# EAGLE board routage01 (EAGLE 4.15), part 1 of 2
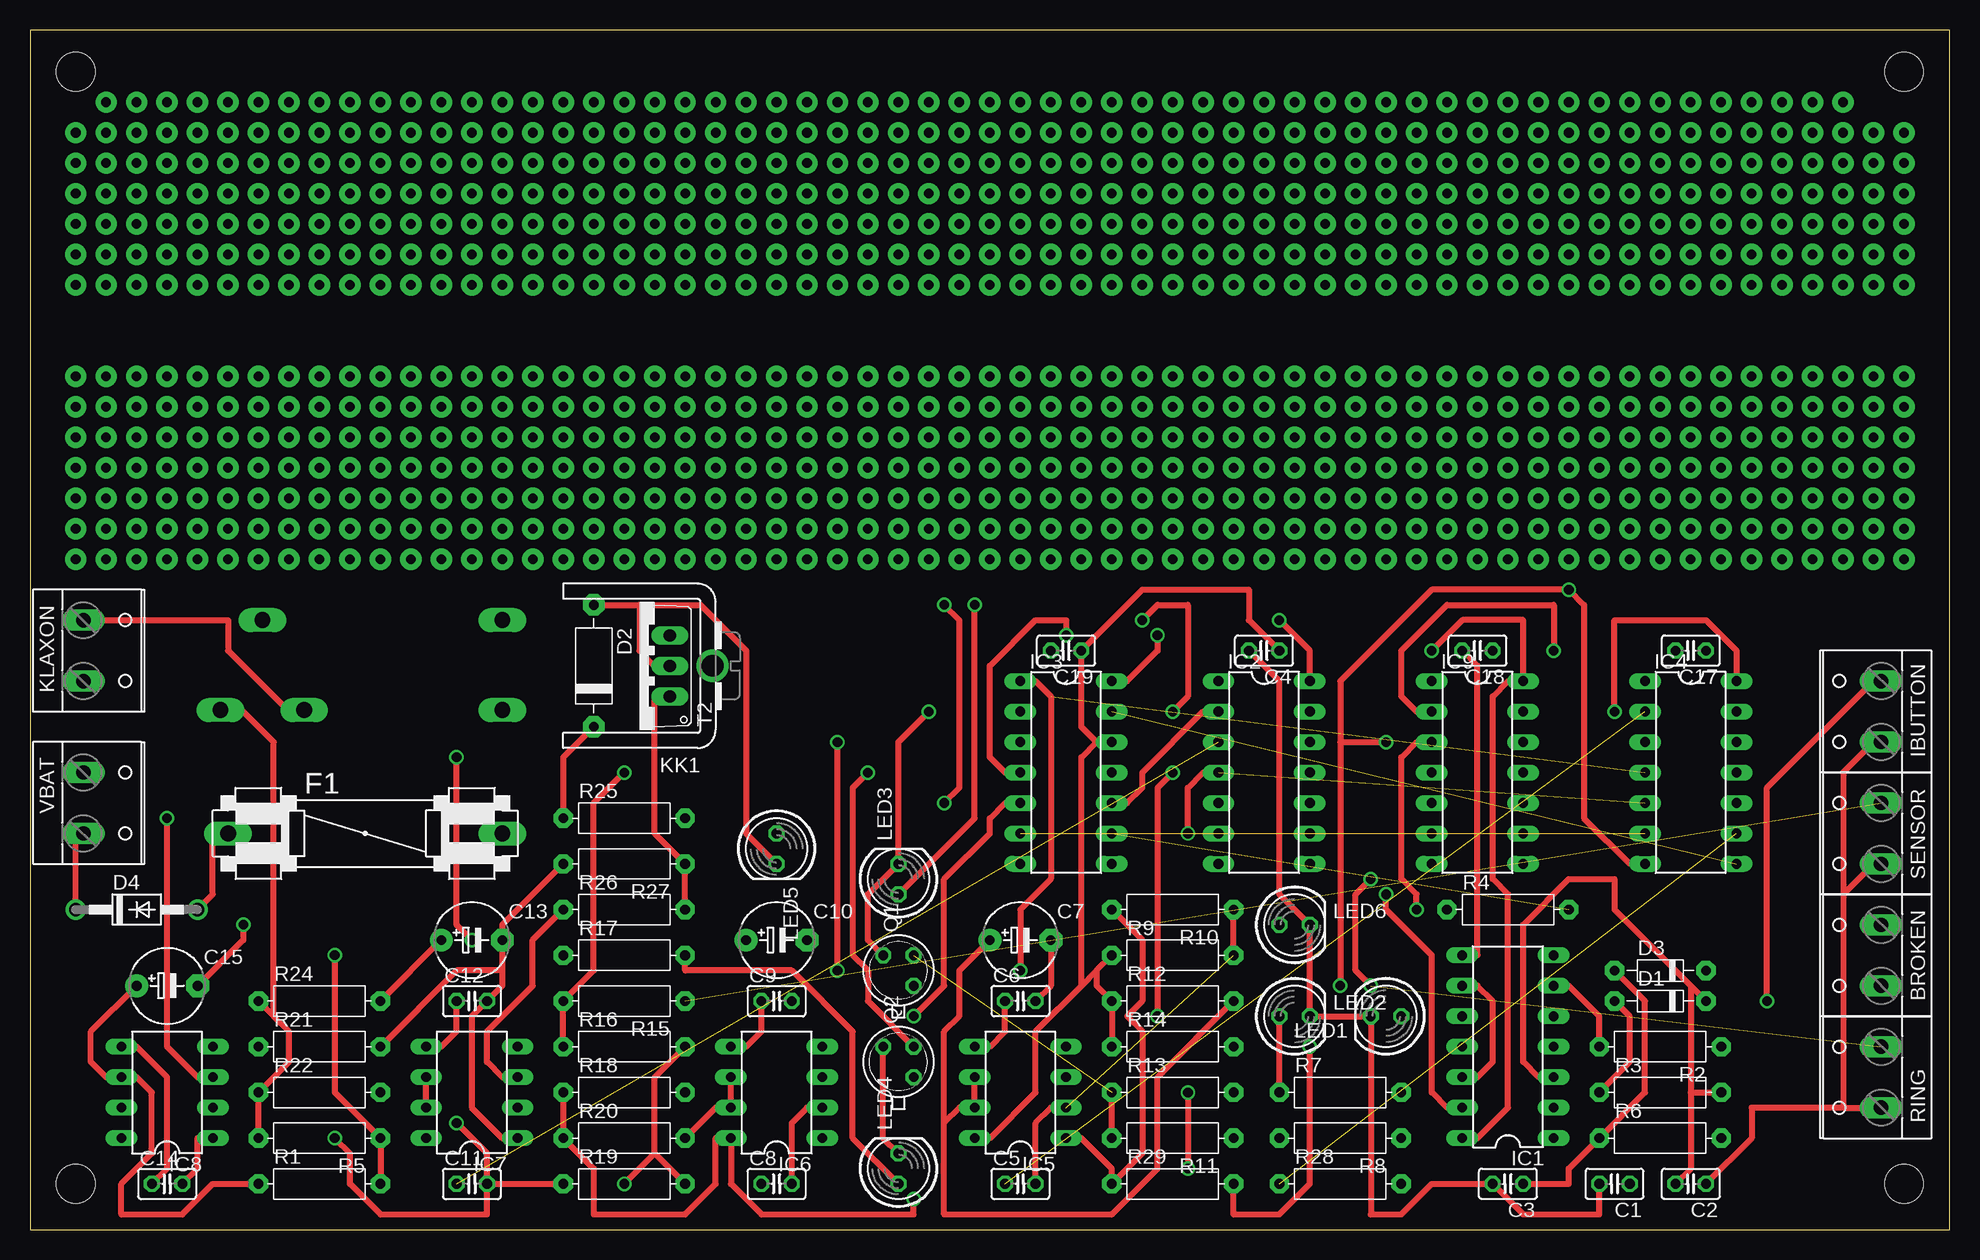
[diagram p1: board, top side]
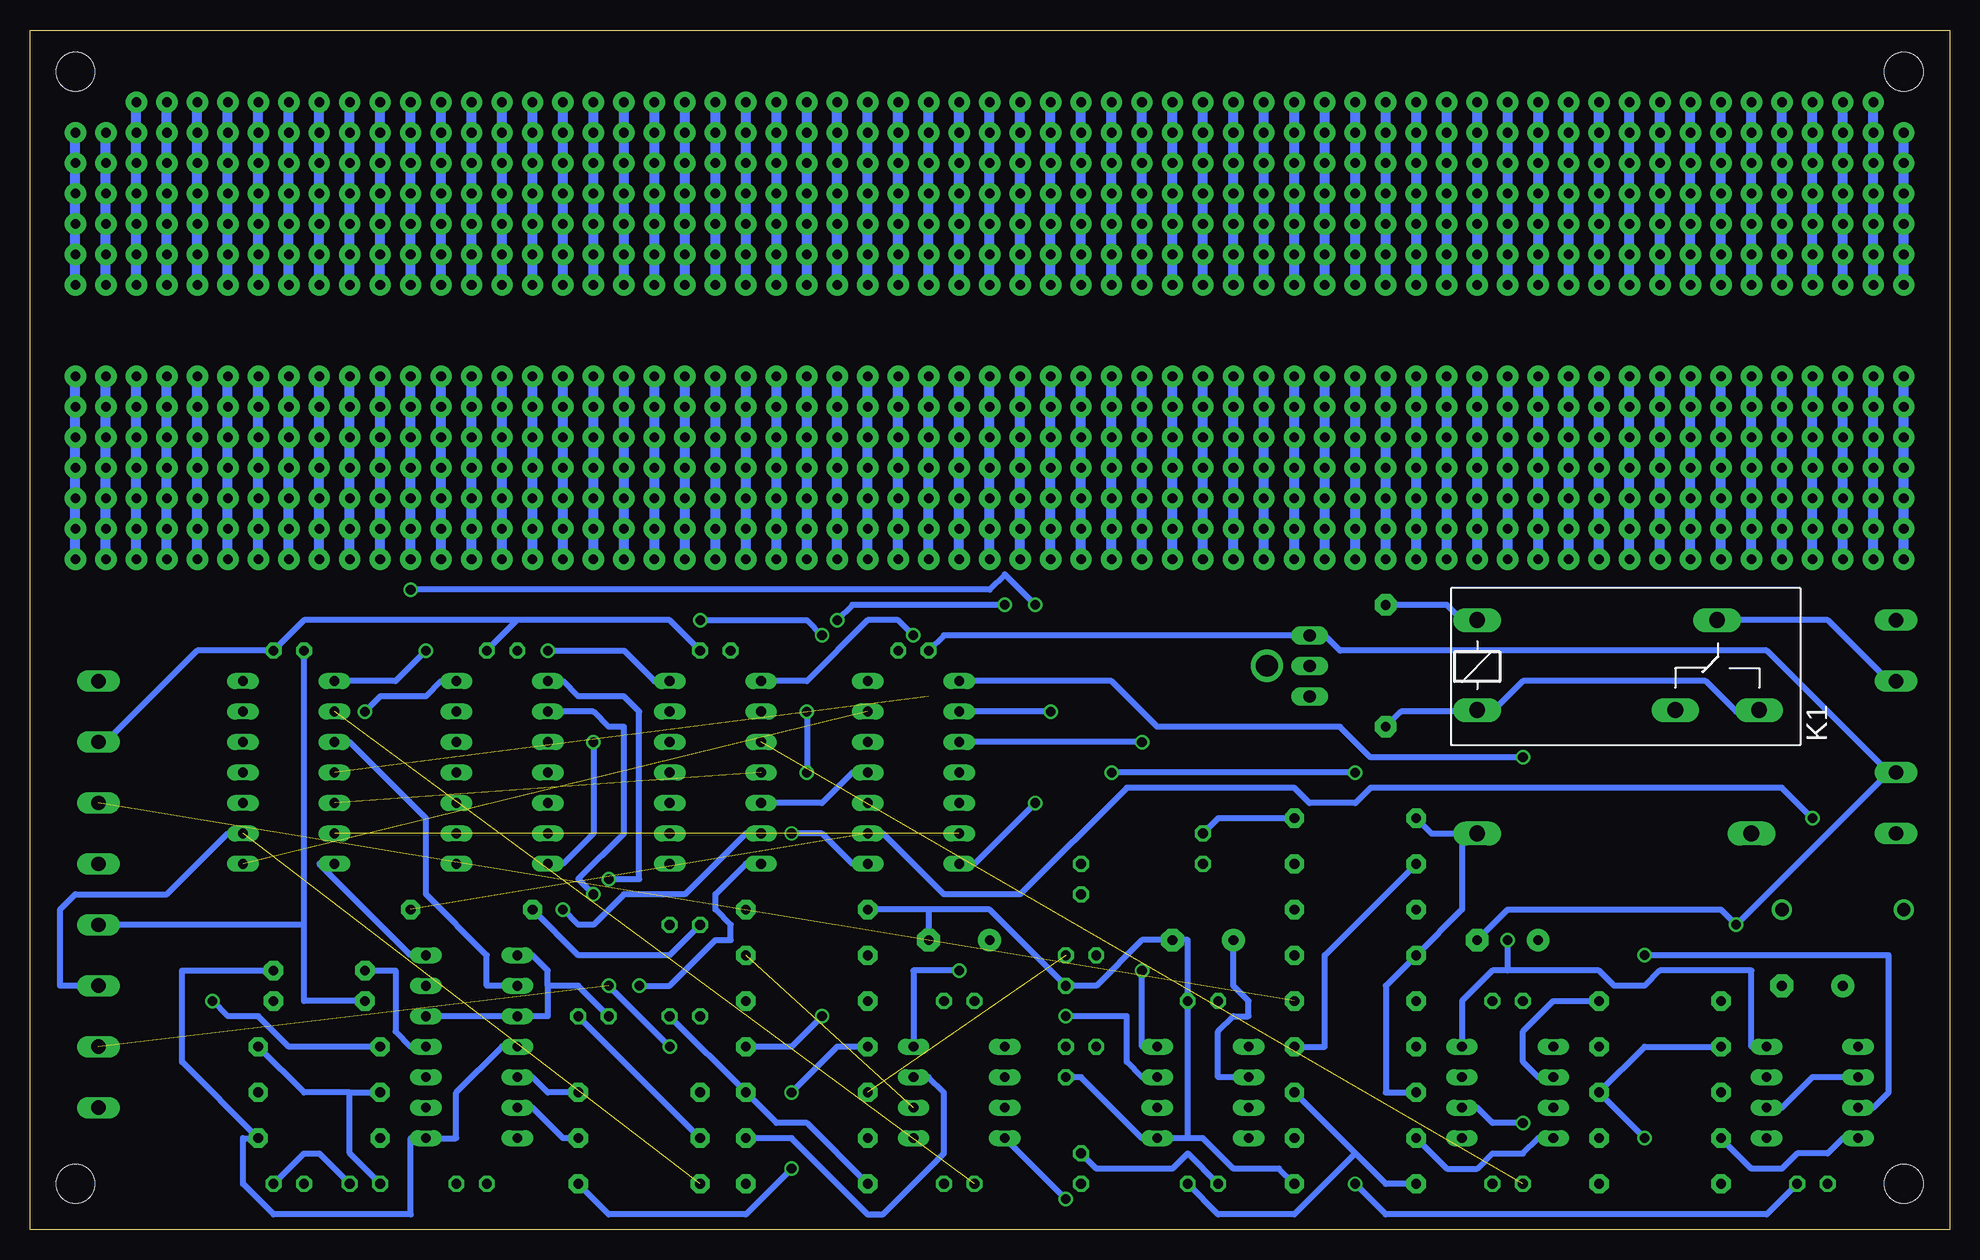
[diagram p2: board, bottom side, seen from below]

Size 160 x 100 mm. Coordinates in mm from the lower left corner, seen from the top.
Outline: 0,0 160,0 160,100 0,100 0,0
Copper layers (1*16): Top 0.035mm / dielectric 1.5mm / Bottom 0.035mm
Design rules "default": minimum track width 10mil, minimum drill 24mil, track to track 8mil, track to pad 8mil, pad to pad 8mil, via to via 8mil, smd to smd 8mil, copper to edge 40mil, drill to drill 8mil, minimum pad ring 10mil, minimum via ring 8mil, stop-mask expansion 4mil, vias tented up to drill 0mil, thermal gap 10mil
Net classes: 0 default: width 0.5 mm, drill 0.5 mm, clearance 0.8 mm
Holes 3.2 mm at 156.21,3.81 156.21,96.52 3.81,96.52 3.81,3.81

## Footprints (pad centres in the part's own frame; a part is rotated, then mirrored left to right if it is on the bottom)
W237-132 = drill 1.194 long: 1 -2.54,-0.635; 2 2.54,-0.635
C025-025X050 = drill 0.813 octagon: 1 -1.27,0; 2 1.27,0
E5-6 = drill 0.813 pad 1.905 round: + -2.54,0 | drill 0.813 pad 1.905 octagon: - 2.54,0
D-7,5 = drill 0.813 pad 1.6 octagon: 1 -3.81,0; 2 3.81,0
D-10 = drill 0.813 pad 1.778 octagon: 1 -5.08,0; 2 5.08,0
DO41-10 = drill 1.118 round: A 5.08,0; C -5.08,0
FUSE = drill 1.321 long: 1 -11.43,0; 2 11.43,0
DIL14 = drill 0.813 long: 1 -7.62,-3.81; 2 -5.08,-3.81; 3 -2.54,-3.81; 4 0,-3.81; 5 2.54,-3.81; 6 5.08,-3.81; 7 7.62,-3.81; 8 7.62,3.81; 9 5.08,3.81; 10 2.54,3.81; 11 0,3.81; 12 -2.54,3.81; 13 -5.08,3.81; 14 -7.62,3.81
DIL08 = drill 0.813 long: 1 -3.81,-3.81; 2 -1.27,-3.81; 3 1.27,-3.81; 4 3.81,-3.81; 5 3.81,3.81; 6 1.27,3.81; 7 -1.27,3.81; 8 -3.81,3.81
G2R = drill 1.321 long: 1 -2.54,-3.683; 2 -2.54,3.81; O 13.97,-3.683; P 17.45,3.81; S 20.955,-3.683
D01PA = drill 1.803 pad 2.54 round: B 0,-1.016
LED5MM = drill 0.813 octagon: A -1.27,0; K 1.27,0
TO18A = drill 0.813 octagon: B 1.27,-1.27; C 1.27,1.27; E -1.27,-1.27
R-10 = drill 0.813 pad 1.6 octagon: 1 -5.08,0; 2 5.08,0
TO220V = drill 1.016 long: 1 -2.54,-2.54; 2 0,-2.54; 3 2.54,-2.54

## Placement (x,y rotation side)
BROKEN  [W237-132]  153.67,22.86 90 top
C1  [C025-025X050]  132.08,3.81 180 top
C2  [C025-025X050]  138.43,3.81 180 top
C3  [C025-025X050]  123.19,3.81 180 top
C4  [C025-025X050]  102.87,48.26 180 top
C5  [C025-025X050]  82.55,3.81 0 top
C6  [C025-025X050]  82.55,19.05 0 top
C7  [E5-6]  82.55,24.13 0 top
C8  [C025-025X050]  62.23,3.81 0 top
C9  [C025-025X050]  62.23,19.05 0 top
C10  [E5-6]  62.23,24.13 0 top
C11  [C025-025X050]  36.83,3.81 0 top
C12  [C025-025X050]  36.83,19.05 0 top
C13  [E5-6]  36.83,24.13 0 top
C14  [C025-025X050]  11.43,3.81 0 top
C15  [E5-6]  11.43,20.32 0 top
C17  [C025-025X050]  138.43,48.26 180 top
C18  [C025-025X050]  120.65,48.26 180 top
C19  [C025-025X050]  86.36,48.26 180 top
D1  [D-7,5]  135.89,19.05 0 top
D2  [D-10]  46.99,46.99 270 top
D3  [D-7,5]  135.89,21.59 0 top
D4  1N4004  [DO41-10]  8.89,26.67 0 top
F1  [FUSE]  27.94,33.02 0 top
IBUTTON  [W237-132]  153.67,43.18 90 top
IC1  4013N  [DIL14]  123.19,15.24 90 top
IC2  4071N  [DIL14]  102.87,38.1 270 top
IC3  4081N  [DIL14]  86.36,38.1 270 top
IC4  4069N  [DIL14]  138.43,38.1 270 top
IC5  NE555N  [DIL08]  82.55,11.43 90 top
IC6  NE555N  [DIL08]  62.23,11.43 90 top
IC7  NE555N  [DIL08]  36.83,11.43 90 top
IC8  NE555N  [DIL08]  11.43,11.43 90 top
IC9  4081N  [DIL14]  120.65,38.1 270 top
K1  G2R  [G2R]  36.83,46.99 0 bottom
KK1  D01PA  [D01PA]  55.88,46.99 90 top
KLAXON  [W237-132]  5.08,48.26 270 top
LED1  [LED5MM]  113.03,17.78 180 top
LED2  [LED5MM]  105.41,17.78 0 top
LED3  [LED5MM]  72.39,29.21 90 top
LED4  [LED5MM]  72.39,5.08 90 top
LED5  [LED5MM]  62.23,31.75 270 top
LED6  [LED5MM]  105.41,25.4 0 top
Q1  2N2222  [TO18A]  72.39,21.59 90 top
Q2  2N2222  [TO18A]  72.39,13.97 90 top
R1  [R-10]  24.13,3.81 0 top
R2  [R-10]  135.89,15.24 180 top
R3  [R-10]  135.89,11.43 0 top
R4  [R-10]  123.19,26.67 0 top
R5  [R-10]  24.13,7.62 180 top
R6  [R-10]  135.89,7.62 0 top
R7  [R-10]  109.22,11.43 0 top
R8  [R-10]  109.22,7.62 180 top
R9  [R-10]  95.25,22.86 0 top
R10  [R-10]  95.25,26.67 180 top
R11  [R-10]  95.25,7.62 180 top
R12  [R-10]  95.25,19.05 0 top
R13  [R-10]  95.25,11.43 0 top
R14  [R-10]  95.25,15.24 0 top
R15  [R-10]  49.53,19.05 180 top
R16  [R-10]  49.53,15.24 0 top
R17  [R-10]  49.53,22.86 0 top
R18  [R-10]  49.53,11.43 0 top
R19  [R-10]  49.53,3.81 0 top
R20  [R-10]  49.53,7.62 0 top
R21  [R-10]  24.13,15.24 0 top
R22  [R-10]  24.13,11.43 0 top
R24  [R-10]  24.13,19.05 0 top
R25  [R-10]  49.53,34.29 0 top
R26  [R-10]  49.53,26.67 0 top
R27  [R-10]  49.53,30.48 180 top
R28  [R-10]  109.22,3.81 0 top
R29  [R-10]  95.25,3.81 0 top
RING  [W237-132]  153.67,12.7 90 top
SENSOR  [W237-132]  153.67,33.02 90 top
T2  [TO220V]  50.8,46.99 90 top
VBAT  [W237-132]  5.08,35.56 270 top

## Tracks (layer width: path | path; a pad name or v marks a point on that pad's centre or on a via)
ACTION  (via drill 0.8)
  Top 0.5: v73.66,17.78 76.2,20.32 76.2,29.21 80.01,33.02 80.01,34.29 81.28,35.56 IC3.5
  Bottom 0.5: v73.66,17.78 68.58,17.78 68.58,13.97 67.31,12.7 IC6.3
ALERTE  (via drill 0.8)  (1 unrouted)
  Top 0.5: v96.52,33.02 96.52,36.83 97.79,38.1 IC2.4
  Bottom 0.5: v96.52,33.02 93.98,33.02 91.44,30.48 IC3.8
ARRACHEMENT  (1 unrouted)
  Bottom 0.5: IC4.9 143.51,33.02 148.59,27.94 156.21,27.94 157.48,26.67 157.48,20.32 BROKEN.1
BP_URGENCE  (via drill 0.8)  (1 unrouted)
  Top 0.5: v111.76,29.21 110.49,27.94 110.49,21.59 v111.76,20.32 | v106.68,15.24 106.68,3.81 104.14,1.27 100.33,1.27 R29.2
  Bottom 0.5: v111.76,29.21 109.22,29.21 109.22,43.18 110.49,44.45 114.3,44.45 115.57,45.72 IC9.1 | v106.68,15.24 v111.76,20.32
CDE
  Top 0.5: R26.1 41.91,24.13 41.91,20.32 38.1,16.51 38.1,13.97 39.37,12.7 IC7.3
CLEAR  (via drill 0.8)
  Top 0.5: v67.31,21.59 v67.31,40.64
  Bottom 0.5: v67.31,21.59 67.31,15.24 IC6.4 | v67.31,40.64 IC3.3
GND  (via drill 0.8)
  Top 0.5: C1.2 130.81,1.27 124.46,1.27 C3.2 116.84,3.81 114.3,1.27 111.76,1.27 LED1.K LED2.K LED6.K 104.14,27.94 104.14,45.72 C4.2 | R3.1 133.35,13.97 133.35,17.78 D1.1 | C18.2 120.65,46.99 120.65,22.86 IC1.8 | IC5.1 87.63,7.62 90.17,5.08 R29.1 92.71,6.35 92.71,16.51 91.44,17.78 92.71,19.05 92.71,24.13 R10.2 | 39.37,21.59 C13.- 39.37,25.4 R27.2 | 39.37,21.59 39.37,20.32 C12.2 36.83,17.78 36.83,10.16 39.37,7.62 IC7.1 | R21.2 35.56,21.59 39.37,21.59 | C6.2 85.09,20.32 C7.- | C14.2 13.97,5.08 13.97,7.62 IC8.1 | R16.2 52.07,12.7 52.07,6.35 | 52.07,6.35 R19.2 | v49.53,3.81 52.07,6.35 | C15.- 17.78,24.13 v17.78,25.4
  Bottom 0.5: 137.16,25.4 137.16,19.05 D1.1 | 137.16,25.4 C17.2 | R2.1 137.16,11.43 133.35,11.43 | 133.35,11.43 R3.1 | 137.16,25.4 BROKEN.2 | C1.2 133.35,6.35 133.35,11.43 | IC1.5 IC1.10 116.84,17.78 116.84,20.32 | 116.84,20.32 116.84,21.59 118.11,22.86 IC1.8 | LED2.K R13.2 97.79,8.89 95.25,8.89 R29.1 | 116.84,20.32 114.3,20.32 LED1.K | 85.09,26.67 R10.2 | 85.09,26.67 80.01,26.67 Q1.E 71.12,20.32 67.31,24.13 C10.- 63.5,24.13 C9.2 63.5,7.62 | 85.09,26.67 C7.- | Q2.E 72.39,12.7 67.31,7.62 IC6.1 63.5,7.62 | R19.2 55.88,5.08 59.69,5.08 62.23,7.62 63.5,7.62 | C14.2 15.24,1.27 46.99,1.27 v49.53,3.81 | R27.2 52.07,22.86 52.07,15.24 R16.2 | C19.2 83.82,49.53 T2.3 52.07,49.53 50.8,48.26 15.24,48.26 5.08,38.1 | 5.08,38.1 v17.78,25.4 19.05,26.67 36.83,26.67 C13.- | 5.08,38.1 VBAT.1
INHIBE  (via drill 0.8)
  Top 0.5: Q1.C 69.85,24.13 69.85,27.94 LED3.K 72.39,40.64 v74.93,43.18
  Bottom 0.5: v74.93,43.18 IC3.2
N$1
  Top 0.5: C3.1 128.27,3.81 128.27,5.08 R6.1 134.62,11.43 134.62,19.05 D3.1
  Bottom 0.5: D3.1 129.54,21.59 129.54,16.51 128.27,15.24 IC1.4
N$2
  Top 0.5: 138.43,20.32 D1.2 | 138.43,20.32 132.08,26.67 132.08,29.21 128.27,29.21 124.46,25.4 124.46,13.97 125.73,12.7 IC1.3 | C2.2 138.43,5.08 138.43,11.43 | 138.43,20.32 138.43,11.43 | 138.43,11.43 R3.2
N$3
  Top 0.5: LED4.A 68.58,7.62 68.58,16.51 63.5,21.59 54.61,21.59 R17.2
N$4
  Top 0.5: R7.1 LED2.A
N$5
  Bottom 0.5: R8.2 LED1.A
N$6  (via drill 0.8)
  Top 0.5: R2.2 130.81,17.78 128.27,20.32 IC1.6 | v144.78,19.05 144.78,36.83 153.67,45.72 IBUTTON.2
  Bottom 0.5: v144.78,19.05 143.51,17.78 140.97,17.78 138.43,15.24 R2.2
N$7
  Bottom 0.5: IC1.11 120.65,15.24 124.46,11.43 124.46,7.62 IC1.1 128.27,7.62 128.27,1.27 139.7,1.27 142.24,3.81 142.24,7.62 R6.2 147.32,13.97 147.32,21.59 D3.2
N$8
  Top 0.5: C6.1 81.28,16.51 80.01,15.24 IC5.5
N$9
  Top 0.5: IC5.6 IC5.7 77.47,10.16 76.2,8.89 | R12.2 93.98,12.7 93.98,5.08 90.17,1.27 76.2,1.27 76.2,8.89 | C7.+ 77.47,21.59 77.47,17.78 76.2,16.51 76.2,8.89
N$10
  Top 0.5: Q2.C 71.12,7.62 LED4.K
  Bottom 0.5: C8.1 63.5,6.35 64.77,5.08 71.12,5.08 LED4.K
N$11
  Bottom 0.5: R11.1 96.52,7.62 90.17,1.27 88.9,1.27 83.82,6.35 83.82,11.43 85.09,12.7 IC5.3
N$12  (1 unrouted)
  Top 0.5: R11.2 R13.1
N$13  (via drill 0.8)
  Top 0.5: Q2.B 69.85,19.05 69.85,21.59 68.58,22.86 68.58,36.83 v69.85,38.1 | v49.53,38.1 46.99,35.56 46.99,21.59 R15.2 R16.1
  Bottom 0.5: v49.53,38.1 v69.85,38.1
N$14  (1 unrouted)
  Top 0.5: R9.2 R10.1 | C5.2 83.82,8.89 85.09,10.16 IC5.2
N$15  (1 unrouted)
N$16
  Top 0.5: C12.1 35.56,16.51 34.29,15.24 IC7.5
N$17
  Top 0.5: C9.1 60.96,16.51 59.69,15.24 IC6.5
N$18  (via drill 0.8)
  Top 0.5: C8.2 63.5,8.89 64.77,10.16 IC6.2 | C11.2 R19.1 | v35.56,8.89 38.1,6.35 C11.2 | v25.4,7.62 26.67,6.35 26.67,3.81 29.21,1.27 38.1,1.27 C11.2
  Bottom 0.5: R21.1 25.4,15.24 R22.2 v25.4,7.62 | v35.56,8.89 38.1,8.89 39.37,10.16 IC7.2 | 49.53,6.35 46.99,3.81 R19.1 | 49.53,6.35 R18.2 | C8.2 60.96,1.27 54.61,1.27 49.53,6.35
N$19  (via drill 0.8)
  Top 0.5: LED3.A 78.74,34.29 v78.74,52.07 | v92.71,50.8 93.98,52.07 96.52,52.07 96.52,44.45 v95.25,43.18 | v95.25,38.1 93.98,36.83 v93.98,17.78
  Bottom 0.5: v78.74,52.07 91.44,52.07 v92.71,50.8 | v95.25,43.18 v95.25,38.1 | v93.98,17.78 96.52,15.24 R14.2
N$20
  Bottom 0.5: LED6.A 106.68,22.86 114.3,22.86 R4.1
N$21
  Top 0.5: T2.1 52.07,44.45 52.07,33.02 R27.1 R26.2
N$22  (1 unrouted)
N$23
  Top 0.5: IC7.7 IC7.6 | R24.2 C13.+
  Bottom 0.5: R24.2 33.02,19.05 35.56,16.51 35.56,13.97 34.29,12.7 IC7.6
N$24
  Top 0.5: LED5.K 59.69,33.02 59.69,48.26 55.88,52.07 50.8,52.07 | D2.1 50.8,52.07 | 50.8,52.07 50.8,48.26 52.07,46.99 T2.2
  Bottom 0.5: D2.1 41.91,52.07 40.64,50.8 K1.2
N$25
  Bottom 0.5: LED5.A 60.96,34.29 R25.2
N$26
  Top 0.5: IC3.10 91.44,35.56 92.71,36.83 92.71,38.1 97.79,43.18 IC2.2
N$27  (via drill 0.8)
  Top 0.5: v86.36,49.53 86.36,50.8 83.82,50.8 80.01,46.99 80.01,39.37 81.28,38.1 IC3.4
  Bottom 0.5: v86.36,49.53 87.63,50.8 90.17,50.8 95.25,45.72 IC2.1
N$28
  Top 0.5: IC6.6 IC6.7 57.15,10.16 R20.2
  Bottom 0.5: C10.+ 59.69,20.32 58.42,19.05 58.42,17.78 59.69,17.78 60.96,16.51 60.96,12.7 IC6.6
N$29  (1 unrouted)
N$30
  Top 0.5: C14.1 11.43,5.08 11.43,12.7 8.89,15.24 IC8.5
N$31  (via drill 0.8)
  Top 0.5: v25.4,22.86 25.4,11.43 R5.1 R1.2
  Bottom 0.5: v25.4,22.86 5.08,22.86 5.08,11.43 6.35,10.16 IC8.7
N$32
  Bottom 0.5: IC3.11 91.44,38.1 93.98,35.56 IC2.5
N$33  (via drill 0.8)
  Top 0.5: v115.57,26.67 115.57,27.94 114.3,29.21 114.3,39.37 115.57,40.64 IC9.3
  Bottom 0.5: v115.57,26.67 114.3,25.4 113.03,25.4 110.49,27.94 105.41,27.94 100.33,33.02 IC2.6
N$34
  Top 0.5: R1.1 15.24,3.81 12.7,1.27 7.62,1.27 7.62,3.81 10.16,6.35 10.16,11.43 8.89,12.7 IC8.6 6.35,12.7 5.08,13.97 5.08,16.51 C15.+
  Bottom 0.5: IC8.2 13.97,10.16 11.43,12.7 IC8.6
N$35
  Top 0.5: D4.A 15.24,27.94 15.24,33.02 F1.1
N$36
  Top 0.5: KLAXON.1 16.51,50.8 16.51,48.26 21.59,43.18 K1.O
N$37
  Top 0.5: D4.C 3.81,33.02 VBAT.2
N$38
  Bottom 0.5: KLAXON.2 5.08,45.72 10.16,50.8 K1.P
N$44  (via drill 0.8 pad 1.78)
  other vias: 92.71,81.28
N$45  (via drill 0.8 pad 1.78)
  other vias: 90.17,83.82
N$46  (via drill 0.8 pad 1.78)
  other vias: 92.71,78.74
N$47  (via drill 0.8 pad 1.78)
  other vias: 113.03,71.12
N$48  (via drill 0.8 pad 1.78)
  other vias: 113.03,68.58
N$49  (via drill 0.8 pad 1.78)
  other vias: 92.71,71.12
N$50  (via drill 0.8 pad 1.78)
  other vias: 92.71,68.58
N$51  (via drill 0.8 pad 1.78)
  other vias: 92.71,66.04
N$52  (via drill 0.8 pad 1.78)
  other vias: 92.71,63.5
N$53  (via drill 0.8 pad 1.78)
  other vias: 92.71,60.96
N$54  (via drill 0.8 pad 1.78)
  other vias: 92.71,58.42
N$55  (via drill 0.8 pad 1.78)
  other vias: 92.71,55.88
N$56  (via drill 0.8 pad 1.78)
  other vias: 92.71,83.82
N$57  (via drill 0.8 pad 1.78)
  other vias: 95.25,83.82
N$58  (via drill 0.8 pad 1.78)
  other vias: 95.25,81.28
N$59  (via drill 0.8 pad 1.78)
  other vias: 95.25,78.74
N$60  (via drill 0.8 pad 1.78)
  other vias: 97.79,83.82
N$61  (via drill 0.8 pad 1.78)
  other vias: 100.33,83.82
N$62  (via drill 0.8 pad 1.78)
  other vias: 100.33,81.28
N$63  (via drill 0.8 pad 1.78)
  other vias: 100.33,78.74
N$64  (via drill 0.8 pad 1.78)
  other vias: 113.03,66.04
N$65  (via drill 0.8 pad 1.78)
  other vias: 113.03,63.5
N$66  (via drill 0.8 pad 1.78)
  other vias: 100.33,71.12
N$67  (via drill 0.8 pad 1.78)
  other vias: 100.33,68.58
N$68  (via drill 0.8 pad 1.78)
  other vias: 97.79,81.28
N$69  (via drill 0.8 pad 1.78)
  other vias: 97.79,78.74
N$70  (via drill 0.8 pad 1.78)
  other vias: 115.57,63.5
N$71  (via drill 0.8 pad 1.78)
  other vias: 102.87,83.82
N$72  (via drill 0.8 pad 1.78)
  other vias: 105.41,83.82
N$73  (via drill 0.8 pad 1.78)
  other vias: 107.95,83.82
N$74  (via drill 0.8 pad 1.78)
  other vias: 110.49,83.82
N$75  (via drill 0.8 pad 1.78)
  other vias: 113.03,83.82
N$76  (via drill 0.8 pad 1.78)
  other vias: 115.57,83.82
N$77  (via drill 0.8 pad 1.78)
  other vias: 118.11,83.82
N$78  (via drill 0.8 pad 1.78)
  other vias: 120.65,83.82
N$79  (via drill 0.8 pad 1.78)
  other vias: 123.19,83.82
N$80  (via drill 0.8 pad 1.78)
  other vias: 125.73,83.82
N$81  (via drill 0.8 pad 1.78)
  other vias: 102.87,81.28
N$82  (via drill 0.8 pad 1.78)
  other vias: 105.41,81.28
N$83  (via drill 0.8 pad 1.78)
  other vias: 105.41,78.74
N$84  (via drill 0.8 pad 1.78)
  other vias: 115.57,71.12
N$85  (via drill 0.8 pad 1.78)
  other vias: 102.87,78.74
N$86  (via drill 0.8 pad 1.78)
  other vias: 118.11,71.12
N$87  (via drill 0.8 pad 1.78)
  other vias: 120.65,71.12
N$88  (via drill 0.8 pad 1.78)
  other vias: 120.65,68.58
N$89  (via drill 0.8 pad 1.78)
  other vias: 105.41,71.12
N$90  (via drill 0.8 pad 1.78)
  other vias: 102.87,71.12
N$91  (via drill 0.8 pad 1.78)
  other vias: 102.87,68.58
N$92  (via drill 0.8 pad 1.78)
  other vias: 105.41,68.58
N$93  (via drill 0.8 pad 1.78)
  other vias: 105.41,66.04
N$94  (via drill 0.8 pad 1.78)
  other vias: 102.87,66.04
N$95  (via drill 0.8 pad 1.78)
  other vias: 100.33,66.04
N$96  (via drill 0.8 pad 1.78)
  other vias: 100.33,63.5
N$97  (via drill 0.8 pad 1.78)
  other vias: 100.33,60.96
N$98  (via drill 0.8 pad 1.78)
  other vias: 100.33,58.42
N$99  (via drill 0.8 pad 1.78)
  other vias: 95.25,55.88
N$100  (via drill 0.8 pad 1.78)
  other vias: 95.25,58.42
N$101  (via drill 0.8 pad 1.78)
  other vias: 95.25,60.96
N$102  (via drill 0.8 pad 1.78)
  other vias: 95.25,63.5
N$103  (via drill 0.8 pad 1.78)
  other vias: 95.25,66.04
N$104  (via drill 0.8 pad 1.78)
  other vias: 95.25,68.58
N$105  (via drill 0.8 pad 1.78)
  other vias: 95.25,71.12
N$106  (via drill 0.8 pad 1.78)
  other vias: 120.65,66.04
N$107  (via drill 0.8 pad 1.78)
  other vias: 118.11,68.58
N$108  (via drill 0.8 pad 1.78)
  other vias: 115.57,68.58
N$109  (via drill 0.8 pad 1.78)
  other vias: 97.79,71.12
N$110  (via drill 0.8 pad 1.78)
  other vias: 97.79,68.58
N$111  (via drill 0.8 pad 1.78)
  other vias: 97.79,66.04
N$112  (via drill 0.8 pad 1.78)
  other vias: 97.79,63.5
N$113  (via drill 0.8 pad 1.78)
  other vias: 97.79,60.96
N$114  (via drill 0.8 pad 1.78)
  other vias: 97.79,58.42
N$115  (via drill 0.8 pad 1.78)
  other vias: 97.79,55.88
N$116  (via drill 0.8 pad 1.78)
  other vias: 107.95,81.28
N$117  (via drill 0.8 pad 1.78)
  other vias: 107.95,78.74
N$118  (via drill 0.8 pad 1.78)
  other vias: 125.73,71.12
N$119  (via drill 0.8 pad 1.78)
  other vias: 125.73,68.58
N$120  (via drill 0.8 pad 1.78)
  other vias: 107.95,71.12
N$121  (via drill 0.8 pad 1.78)
  other vias: 107.95,68.58
N$122  (via drill 0.8 pad 1.78)
  other vias: 107.95,66.04
N$123  (via drill 0.8 pad 1.78)
  other vias: 107.95,63.5
N$124  (via drill 0.8 pad 1.78)
  other vias: 107.95,60.96
N$125  (via drill 0.8 pad 1.78)
  other vias: 107.95,58.42
N$126  (via drill 0.8 pad 1.78)
  other vias: 107.95,55.88
N$127  (via drill 0.8 pad 1.78)
  other vias: 105.41,55.88
N$128  (via drill 0.8 pad 1.78)
  other vias: 102.87,55.88
N$129  (via drill 0.8 pad 1.78)
  other vias: 105.41,58.42
N$130  (via drill 0.8 pad 1.78)
  other vias: 105.41,60.96
N$131  (via drill 0.8 pad 1.78)
  other vias: 105.41,63.5
N$132  (via drill 0.8 pad 1.78)
  other vias: 102.87,63.5
N$133  (via drill 0.8 pad 1.78)
  other vias: 102.87,60.96
N$134  (via drill 0.8 pad 1.78)
  other vias: 102.87,58.42
N$135  (via drill 0.8 pad 1.78)
  other vias: 110.49,55.88
N$136  (via drill 0.8 pad 1.78)
  other vias: 113.03,55.88
N$137  (via drill 0.8 pad 1.78)
  other vias: 115.57,55.88
N$138  (via drill 0.8 pad 1.78)
  other vias: 118.11,55.88
N$139  (via drill 0.8 pad 1.78)
  other vias: 120.65,55.88
N$140  (via drill 0.8 pad 1.78)
  other vias: 123.19,55.88
N$141  (via drill 0.8 pad 1.78)
  other vias: 125.73,55.88
N$142  (via drill 0.8 pad 1.78)
  other vias: 128.27,55.88
N$143  (via drill 0.8 pad 1.78)
  other vias: 130.81,55.88
N$144  (via drill 0.8 pad 1.78)
  other vias: 133.35,55.88
N$145  (via drill 0.8 pad 1.78)
  other vias: 135.89,55.88
N$146  (via drill 0.8 pad 1.78)
  other vias: 138.43,55.88
N$147  (via drill 0.8 pad 1.78)
  other vias: 140.97,55.88
N$148  (via drill 0.8 pad 1.78)
  other vias: 143.51,55.88
N$149  (via drill 0.8 pad 1.78)
  other vias: 146.05,55.88
N$150  (via drill 0.8 pad 1.78)
  other vias: 148.59,55.88
N$151  (via drill 0.8 pad 1.78)
  other vias: 151.13,55.88
N$152  (via drill 0.8 pad 1.78)
  other vias: 153.67,55.88
N$153  (via drill 0.8 pad 1.78)
  other vias: 156.21,55.88
N$154  (via drill 0.8 pad 1.78)
  other vias: 156.21,58.42
N$155  (via drill 0.8 pad 1.78)
  other vias: 153.67,58.42
N$156  (via drill 0.8 pad 1.78)
  other vias: 110.49,81.28
N$157  (via drill 0.8 pad 1.78)
  other vias: 110.49,58.42
N$158  (via drill 0.8 pad 1.78)
  other vias: 110.49,60.96
N$159  (via drill 0.8 pad 1.78)
  other vias: 110.49,63.5
N$160  (via drill 0.8 pad 1.78)
  other vias: 110.49,66.04
N$161  (via drill 0.8 pad 1.78)
  other vias: 110.49,68.58
N$162  (via drill 0.8 pad 1.78)
  other vias: 110.49,71.12
N$163  (via drill 0.8 pad 1.78)
  other vias: 125.73,66.04
N$164  (via drill 0.8 pad 1.78)
  other vias: 125.73,63.5
N$165  (via drill 0.8 pad 1.78)
  other vias: 110.49,78.74
N$166  (via drill 0.8 pad 1.78)
  other vias: 125.73,78.74
N$167  (via drill 0.8 pad 1.78)
  other vias: 64.77,55.88
N$168  (via drill 0.8 pad 1.78)
  other vias: 62.23,55.88
N$169  (via drill 0.8 pad 1.78)
  other vias: 123.19,71.12
N$170  (via drill 0.8 pad 1.78)
  other vias: 123.19,68.58
N$171  (via drill 0.8 pad 1.78)
  other vias: 123.19,66.04
N$172  (via drill 0.8 pad 1.78)
  other vias: 123.19,63.5
N$173  (via drill 0.8 pad 1.78)
  other vias: 123.19,58.42
N$174  (via drill 0.8 pad 1.78)
  other vias: 120.65,58.42
N$175  (via drill 0.8 pad 1.78)
  other vias: 128.27,58.42
N$176  (via drill 0.8 pad 1.78)
  other vias: 128.27,60.96
N$177  (via drill 0.8 pad 1.78)
  other vias: 125.73,58.42
N$178  (via drill 0.8 pad 1.78)
  other vias: 125.73,60.96
N$179  (via drill 0.8 pad 1.78)
  other vias: 123.19,60.96
N$180  (via drill 0.8 pad 1.78)
  other vias: 113.03,60.96
N$181  (via drill 0.8 pad 1.78)
  other vias: 115.57,60.96
N$182  (via drill 0.8 pad 1.78)
  other vias: 118.11,60.96
N$183  (via drill 0.8 pad 1.78)
  other vias: 120.65,60.96
N$184  (via drill 0.8 pad 1.78)
  other vias: 120.65,63.5
N$185  (via drill 0.8 pad 1.78)
  other vias: 118.11,63.5
N$186  (via drill 0.8 pad 1.78)
  other vias: 133.35,60.96
N$187  (via drill 0.8 pad 1.78)
  other vias: 118.11,66.04
N$188  (via drill 0.8 pad 1.78)
  other vias: 115.57,66.04
N$189  (via drill 0.8 pad 1.78)
  other vias: 135.89,60.96
N$190  (via drill 0.8 pad 1.78)
  other vias: 135.89,63.5
N$191  (via drill 0.8 pad 1.78)
  other vias: 133.35,63.5
N$192  (via drill 0.8 pad 1.78)
  other vias: 130.81,63.5
N$193  (via drill 0.8 pad 1.78)
  other vias: 128.27,63.5
N$194  (via drill 0.8 pad 1.78)
  other vias: 115.57,81.28
N$195  (via drill 0.8 pad 1.78)
  other vias: 100.33,55.88
N$196  (via drill 0.8 pad 1.78)
  other vias: 113.03,58.42
N$197  (via drill 0.8 pad 1.78)
  other vias: 118.11,58.42
N$198  (via drill 0.8 pad 1.78)
  other vias: 115.57,58.42
N$199  (via drill 0.8 pad 1.78)
  other vias: 135.89,58.42
N$200  (via drill 0.8 pad 1.78)
  other vias: 133.35,58.42
N$201  (via drill 0.8 pad 1.78)
  other vias: 130.81,58.42
N$202  (via drill 0.8 pad 1.78)
  other vias: 130.81,60.96
N$203  (via drill 0.8 pad 1.78)
  other vias: 128.27,66.04
N$204  (via drill 0.8 pad 1.78)
  other vias: 128.27,68.58
N$205  (via drill 0.8 pad 1.78)
  other vias: 128.27,71.12
N$206  (via drill 0.8 pad 1.78)
  other vias: 130.81,71.12
N$207  (via drill 0.8 pad 1.78)
  other vias: 130.81,68.58
N$208  (via drill 0.8 pad 1.78)
  other vias: 130.81,66.04
N$209  (via drill 0.8 pad 1.78)
  other vias: 133.35,66.04
N$210  (via drill 0.8 pad 1.78)
  other vias: 135.89,66.04
N$211  (via drill 0.8 pad 1.78)
  other vias: 135.89,68.58
N$212  (via drill 0.8 pad 1.78)
  other vias: 133.35,68.58
N$213  (via drill 0.8 pad 1.78)
  other vias: 133.35,71.12
N$214  (via drill 0.8 pad 1.78)
  other vias: 135.89,71.12
N$215  (via drill 0.8 pad 1.78)
  other vias: 146.05,58.42
N$216  (via drill 0.8 pad 1.78)
  other vias: 143.51,58.42
N$217  (via drill 0.8 pad 1.78)
  other vias: 140.97,58.42
N$218  (via drill 0.8 pad 1.78)
  other vias: 138.43,58.42
N$219  (via drill 0.8 pad 1.78)
  other vias: 138.43,60.96
N$220  (via drill 0.8 pad 1.78)
  other vias: 138.43,63.5
N$221  (via drill 0.8 pad 1.78)
  other vias: 138.43,66.04
N$222  (via drill 0.8 pad 1.78)
  other vias: 138.43,68.58
N$223  (via drill 0.8 pad 1.78)
  other vias: 138.43,71.12
N$224  (via drill 0.8 pad 1.78)
  other vias: 146.05,60.96
N$225  (via drill 0.8 pad 1.78)
  other vias: 146.05,63.5
N$226  (via drill 0.8 pad 1.78)
  other vias: 146.05,66.04
N$227  (via drill 0.8 pad 1.78)
  other vias: 146.05,68.58
N$228  (via drill 0.8 pad 1.78)
  other vias: 146.05,71.12
N$229  (via drill 0.8 pad 1.78)
  other vias: 143.51,71.12
N$230  (via drill 0.8 pad 1.78)
  other vias: 140.97,71.12
N$231  (via drill 0.8 pad 1.78)
  other vias: 140.97,68.58
N$232  (via drill 0.8 pad 1.78)
  other vias: 143.51,68.58
N$233  (via drill 0.8 pad 1.78)
  other vias: 143.51,66.04
N$234  (via drill 0.8 pad 1.78)
  other vias: 143.51,63.5
N$235  (via drill 0.8 pad 1.78)
  other vias: 143.51,60.96
N$236  (via drill 0.8 pad 1.78)
  other vias: 140.97,60.96
N$237  (via drill 0.8 pad 1.78)
  other vias: 140.97,63.5
N$238  (via drill 0.8 pad 1.78)
  other vias: 140.97,66.04
N$239  (via drill 0.8 pad 1.78)
  other vias: 148.59,58.42
N$240  (via drill 0.8 pad 1.78)
  other vias: 148.59,60.96
N$241  (via drill 0.8 pad 1.78)
  other vias: 151.13,58.42
N$242  (via drill 0.8 pad 1.78)
  other vias: 148.59,63.5
N$243  (via drill 0.8 pad 1.78)
  other vias: 148.59,66.04
N$244  (via drill 0.8 pad 1.78)
  other vias: 148.59,68.58
N$245  (via drill 0.8 pad 1.78)
  other vias: 148.59,71.12
N$246  (via drill 0.8 pad 1.78)
  other vias: 151.13,71.12
N$247  (via drill 0.8 pad 1.78)
  other vias: 151.13,68.58
N$248  (via drill 0.8 pad 1.78)
  other vias: 151.13,66.04
N$249  (via drill 0.8 pad 1.78)
  other vias: 151.13,63.5
N$250  (via drill 0.8 pad 1.78)
  other vias: 151.13,60.96
N$251  (via drill 0.8 pad 1.78)
  other vias: 153.67,60.96
N$252  (via drill 0.8 pad 1.78)
  other vias: 156.21,60.96
N$253  (via drill 0.8 pad 1.78)
  other vias: 156.21,63.5
N$254  (via drill 0.8 pad 1.78)
  other vias: 153.67,63.5
N$255  (via drill 0.8 pad 1.78)
  other vias: 156.21,66.04
N$256  (via drill 0.8 pad 1.78)
  other vias: 153.67,66.04
N$257  (via drill 0.8 pad 1.78)
  other vias: 153.67,68.58
N$258  (via drill 0.8 pad 1.78)
  other vias: 156.21,68.58
N$259  (via drill 0.8 pad 1.78)
  other vias: 156.21,71.12
N$260  (via drill 0.8 pad 1.78)
  other vias: 153.67,71.12
N$261  (via drill 0.8 pad 1.78)
  other vias: 90.17,55.88
N$262  (via drill 0.8 pad 1.78)
  other vias: 87.63,55.88
N$263  (via drill 0.8 pad 1.78)
  other vias: 85.09,55.88
N$264  (via drill 0.8 pad 1.78)
  other vias: 82.55,55.88
N$265  (via drill 0.8 pad 1.78)
  other vias: 80.01,55.88
N$266  (via drill 0.8 pad 1.78)
  other vias: 77.47,55.88
N$267  (via drill 0.8 pad 1.78)
  other vias: 74.93,55.88
N$268  (via drill 0.8 pad 1.78)
  other vias: 72.39,55.88
N$269  (via drill 0.8 pad 1.78)
  other vias: 69.85,55.88
N$270  (via drill 0.8 pad 1.78)
  other vias: 67.31,55.88
N$271  (via drill 0.8 pad 1.78)
  other vias: 90.17,58.42
N$272  (via drill 0.8 pad 1.78)
  other vias: 80.01,66.04
N$273  (via drill 0.8 pad 1.78)
  other vias: 80.01,60.96
N$274  (via drill 0.8 pad 1.78)
  other vias: 80.01,58.42
N$275  (via drill 0.8 pad 1.78)
  other vias: 82.55,58.42
N$276  (via drill 0.8 pad 1.78)
  other vias: 82.55,60.96
N$277  (via drill 0.8 pad 1.78)
  other vias: 82.55,71.12
N$278  (via drill 0.8 pad 1.78)
  other vias: 82.55,68.58
N$279  (via drill 0.8 pad 1.78)
  other vias: 82.55,66.04
N$280  (via drill 0.8 pad 1.78)
  other vias: 82.55,63.5
N$281  (via drill 0.8 pad 1.78)
  other vias: 72.39,58.42
N$282  (via drill 0.8 pad 1.78)
  other vias: 72.39,60.96
N$283  (via drill 0.8 pad 1.78)
  other vias: 72.39,63.5
N$284  (via drill 0.8 pad 1.78)
  other vias: 72.39,66.04
N$285  (via drill 0.8 pad 1.78)
  other vias: 72.39,68.58
N$286  (via drill 0.8 pad 1.78)
  other vias: 72.39,71.12
N$287  (via drill 0.8 pad 1.78)
  other vias: 67.31,58.42
N$288  (via drill 0.8 pad 1.78)
  other vias: 67.31,60.96
N$289  (via drill 0.8 pad 1.78)
  other vias: 67.31,63.5
N$290  (via drill 0.8 pad 1.78)
  other vias: 67.31,71.12
N$291  (via drill 0.8 pad 1.78)
  other vias: 67.31,68.58
N$292  (via drill 0.8 pad 1.78)
  other vias: 67.31,66.04
N$293  (via drill 0.8 pad 1.78)
  other vias: 69.85,58.42
N$294  (via drill 0.8 pad 1.78)
  other vias: 69.85,60.96
N$295  (via drill 0.8 pad 1.78)
  other vias: 69.85,63.5
N$296  (via drill 0.8 pad 1.78)
  other vias: 69.85,66.04
N$297  (via drill 0.8 pad 1.78)
  other vias: 69.85,68.58
N$298  (via drill 0.8 pad 1.78)
  other vias: 69.85,71.12
N$299  (via drill 0.8 pad 1.78)
  other vias: 74.93,71.12
N$300  (via drill 0.8 pad 1.78)
  other vias: 74.93,68.58
N$301  (via drill 0.8 pad 1.78)
  other vias: 74.93,66.04
N$302  (via drill 0.8 pad 1.78)
  other vias: 74.93,63.5
N$303  (via drill 0.8 pad 1.78)
  other vias: 74.93,60.96
N$304  (via drill 0.8 pad 1.78)
  other vias: 74.93,58.42
N$305  (via drill 0.8 pad 1.78)
  other vias: 77.47,58.42
N$306  (via drill 0.8 pad 1.78)
  other vias: 77.47,60.96
N$307  (via drill 0.8 pad 1.78)
  other vias: 77.47,63.5
N$308  (via drill 0.8 pad 1.78)
  other vias: 77.47,66.04
N$309  (via drill 0.8 pad 1.78)
  other vias: 77.47,68.58
N$310  (via drill 0.8 pad 1.78)
  other vias: 77.47,71.12
N$311  (via drill 0.8 pad 1.78)
  other vias: 80.01,71.12
N$312  (via drill 0.8 pad 1.78)
  other vias: 80.01,68.58
N$313  (via drill 0.8 pad 1.78)
  other vias: 90.17,71.12
N$314  (via drill 0.8 pad 1.78)
  other vias: 87.63,71.12
N$315  (via drill 0.8 pad 1.78)
  other vias: 85.09,71.12
N$316  (via drill 0.8 pad 1.78)
  other vias: 85.09,68.58
N$317  (via drill 0.8 pad 1.78)
  other vias: 85.09,66.04
N$318  (via drill 0.8 pad 1.78)
  other vias: 85.09,63.5
N$319  (via drill 0.8 pad 1.78)
  other vias: 85.09,60.96
N$320  (via drill 0.8 pad 1.78)
  other vias: 87.63,58.42
N$321  (via drill 0.8 pad 1.78)
  other vias: 85.09,58.42
N$322  (via drill 0.8 pad 1.78)
  other vias: 87.63,60.96
N$323  (via drill 0.8 pad 1.78)
  other vias: 90.17,60.96
N$324  (via drill 0.8 pad 1.78)
  other vias: 90.17,63.5
N$325  (via drill 0.8 pad 1.78)
  other vias: 87.63,63.5
N$326  (via drill 0.8 pad 1.78)
  other vias: 87.63,66.04
N$327  (via drill 0.8 pad 1.78)
  other vias: 90.17,66.04
N$328  (via drill 0.8 pad 1.78)
  other vias: 90.17,68.58
N$329  (via drill 0.8 pad 1.78)
  other vias: 87.63,68.58
N$330  (via drill 0.8 pad 1.78)
  other vias: 80.01,63.5
N$331  (via drill 0.8 pad 1.78)
  other vias: 90.17,78.74
N$332  (via drill 0.8 pad 1.78)
  other vias: 87.63,78.74
N$333  (via drill 0.8 pad 1.78)
  other vias: 85.09,78.74
N$334  (via drill 0.8 pad 1.78)
  other vias: 82.55,78.74
N$335  (via drill 0.8 pad 1.78)
  other vias: 80.01,78.74
N$336  (via drill 0.8 pad 1.78)
  other vias: 77.47,78.74
N$337  (via drill 0.8 pad 1.78)
  other vias: 74.93,78.74
N$338  (via drill 0.8 pad 1.78)
  other vias: 72.39,78.74
N$339  (via drill 0.8 pad 1.78)
  other vias: 69.85,78.74
N$340  (via drill 0.8 pad 1.78)
  other vias: 67.31,78.74
N$341  (via drill 0.8 pad 1.78)
  other vias: 67.31,81.28
N$342  (via drill 0.8 pad 1.78)
  other vias: 67.31,83.82
N$343  (via drill 0.8 pad 1.78)
  other vias: 67.31,86.36
N$344  (via drill 0.8 pad 1.78)
  other vias: 67.31,88.9
N$345  (via drill 0.8 pad 1.78)
  other vias: 67.31,91.44
N$346  (via drill 0.8 pad 1.78)
  other vias: 67.31,93.98
N$347  (via drill 0.8 pad 1.78)
  other vias: 69.85,81.28
N$348  (via drill 0.8 pad 1.78)
  other vias: 69.85,83.82
N$349  (via drill 0.8 pad 1.78)
  other vias: 69.85,86.36
N$350  (via drill 0.8 pad 1.78)
  other vias: 69.85,88.9
N$351  (via drill 0.8 pad 1.78)
  other vias: 69.85,91.44
N$352  (via drill 0.8 pad 1.78)
  other vias: 69.85,93.98
N$353  (via drill 0.8 pad 1.78)
  other vias: 72.39,81.28
N$354  (via drill 0.8 pad 1.78)
  other vias: 72.39,83.82
N$355  (via drill 0.8 pad 1.78)
  other vias: 72.39,86.36
N$356  (via drill 0.8 pad 1.78)
  other vias: 72.39,88.9
N$357  (via drill 0.8 pad 1.78)
  other vias: 72.39,91.44
N$358  (via drill 0.8 pad 1.78)
  other vias: 72.39,93.98
N$359  (via drill 0.8 pad 1.78)
  other vias: 80.01,81.28
N$360  (via drill 0.8 pad 1.78)
  other vias: 77.47,81.28
N$361  (via drill 0.8 pad 1.78)
  other vias: 74.93,81.28
N$362  (via drill 0.8 pad 1.78)
  other vias: 80.01,83.82
N$363  (via drill 0.8 pad 1.78)
  other vias: 80.01,86.36
N$364  (via drill 0.8 pad 1.78)
  other vias: 80.01,88.9
N$365  (via drill 0.8 pad 1.78)
  other vias: 80.01,91.44
N$366  (via drill 0.8 pad 1.78)
  other vias: 80.01,93.98
N$367  (via drill 0.8 pad 1.78)
  other vias: 77.47,93.98
N$368  (via drill 0.8 pad 1.78)
  other vias: 77.47,91.44
N$369  (via drill 0.8 pad 1.78)
  other vias: 74.93,93.98
N$370  (via drill 0.8 pad 1.78)
  other vias: 74.93,91.44
N$371  (via drill 0.8 pad 1.78)
  other vias: 74.93,88.9
N$372  (via drill 0.8 pad 1.78)
  other vias: 74.93,86.36
N$373  (via drill 0.8 pad 1.78)
  other vias: 74.93,83.82
N$374  (via drill 0.8 pad 1.78)
  other vias: 77.47,83.82
N$375  (via drill 0.8 pad 1.78)
  other vias: 77.47,86.36
N$376  (via drill 0.8 pad 1.78)
  other vias: 77.47,88.9
N$377  (via drill 0.8 pad 1.78)
  other vias: 82.55,81.28
N$378  (via drill 0.8 pad 1.78)
  other vias: 82.55,83.82
N$379  (via drill 0.8 pad 1.78)
  other vias: 82.55,86.36
N$380  (via drill 0.8 pad 1.78)
  other vias: 82.55,88.9
N$381  (via drill 0.8 pad 1.78)
  other vias: 82.55,91.44
N$382  (via drill 0.8 pad 1.78)
  other vias: 82.55,93.98
N$383  (via drill 0.8 pad 1.78)
  other vias: 128.27,78.74
N$384  (via drill 0.8 pad 1.78)
  other vias: 130.81,78.74
N$385  (via drill 0.8 pad 1.78)
  other vias: 133.35,78.74
N$386  (via drill 0.8 pad 1.78)
  other vias: 135.89,78.74
N$387  (via drill 0.8 pad 1.78)
  other vias: 135.89,81.28
N$388  (via drill 0.8 pad 1.78)
  other vias: 135.89,83.82
N$389  (via drill 0.8 pad 1.78)
  other vias: 128.27,83.82
N$390  (via drill 0.8 pad 1.78)
  other vias: 130.81,83.82
N$391  (via drill 0.8 pad 1.78)
  other vias: 133.35,83.82
N$392  (via drill 0.8 pad 1.78)
  other vias: 133.35,81.28
N$393  (via drill 0.8 pad 1.78)
  other vias: 130.81,81.28
N$394  (via drill 0.8 pad 1.78)
  other vias: 128.27,81.28
N$395  (via drill 0.8 pad 1.78)
  other vias: 125.73,81.28
N$396  (via drill 0.8 pad 1.78)
  other vias: 123.19,81.28
N$397  (via drill 0.8 pad 1.78)
  other vias: 85.09,81.28
N$398  (via drill 0.8 pad 1.78)
  other vias: 118.11,81.28
N$399  (via drill 0.8 pad 1.78)
  other vias: 123.19,78.74
N$400  (via drill 0.8 pad 1.78)
  other vias: 120.65,78.74
N$401  (via drill 0.8 pad 1.78)
  other vias: 118.11,78.74
N$402  (via drill 0.8 pad 1.78)
  other vias: 115.57,78.74
N$403  (via drill 0.8 pad 1.78)
  other vias: 113.03,78.74
N$404  (via drill 0.8 pad 1.78)
  other vias: 113.03,81.28
N$405  (via drill 0.8 pad 1.78)
  other vias: 120.65,81.28
N$406  (via drill 0.8 pad 1.78)
  other vias: 92.71,86.36
N$407  (via drill 0.8 pad 1.78)
  other vias: 90.17,86.36
N$408  (via drill 0.8 pad 1.78)
  other vias: 87.63,86.36
N$409  (via drill 0.8 pad 1.78)
  other vias: 85.09,86.36
N$410  (via drill 0.8 pad 1.78)
  other vias: 85.09,83.82
N$411  (via drill 0.8 pad 1.78)
  other vias: 87.63,83.82
N$412  (via drill 0.8 pad 1.78)
  other vias: 87.63,81.28
N$413  (via drill 0.8 pad 1.78)
  other vias: 90.17,81.28
N$414  (via drill 0.8 pad 1.78)
  other vias: 135.89,86.36
N$415  (via drill 0.8 pad 1.78)
  other vias: 135.89,88.9
N$416  (via drill 0.8 pad 1.78)
  other vias: 135.89,91.44
N$417  (via drill 0.8 pad 1.78)
  other vias: 133.35,91.44
N$418  (via drill 0.8 pad 1.78)
  other vias: 133.35,88.9
N$419  (via drill 0.8 pad 1.78)
  other vias: 133.35,86.36
N$420  (via drill 0.8 pad 1.78)
  other vias: 130.81,86.36
N$421  (via drill 0.8 pad 1.78)
  other vias: 128.27,86.36
N$422  (via drill 0.8 pad 1.78)
  other vias: 125.73,86.36
N$423  (via drill 0.8 pad 1.78)
  other vias: 125.73,88.9
N$424  (via drill 0.8 pad 1.78)
  other vias: 128.27,88.9
N$425  (via drill 0.8 pad 1.78)
  other vias: 130.81,88.9
N$426  (via drill 0.8 pad 1.78)
  other vias: 130.81,91.44
N$427  (via drill 0.8 pad 1.78)
  other vias: 128.27,91.44
N$428  (via drill 0.8 pad 1.78)
  other vias: 125.73,91.44
N$429  (via drill 0.8 pad 1.78)
  other vias: 138.43,78.74
N$430  (via drill 0.8 pad 1.78)
  other vias: 156.21,78.74
N$431  (via drill 0.8 pad 1.78)
  other vias: 153.67,78.74
N$432  (via drill 0.8 pad 1.78)
  other vias: 156.21,91.44
N$433  (via drill 0.8 pad 1.78)
  other vias: 153.67,91.44
N$434  (via drill 0.8 pad 1.78)
  other vias: 151.13,91.44
N$435  (via drill 0.8 pad 1.78)
  other vias: 148.59,91.44
N$436  (via drill 0.8 pad 1.78)
  other vias: 146.05,91.44
N$437  (via drill 0.8 pad 1.78)
  other vias: 143.51,91.44
N$438  (via drill 0.8 pad 1.78)
  other vias: 140.97,91.44
N$439  (via drill 0.8 pad 1.78)
  other vias: 138.43,91.44
N$440  (via drill 0.8 pad 1.78)
  other vias: 138.43,88.9
N$441  (via drill 0.8 pad 1.78)
  other vias: 138.43,86.36
N$442  (via drill 0.8 pad 1.78)
  other vias: 138.43,83.82
N$443  (via drill 0.8 pad 1.78)
  other vias: 138.43,81.28
N$444  (via drill 0.8 pad 1.78)
  other vias: 140.97,78.74
N$445  (via drill 0.8 pad 1.78)
  other vias: 143.51,78.74
N$446  (via drill 0.8 pad 1.78)
  other vias: 146.05,78.74
N$447  (via drill 0.8 pad 1.78)
  other vias: 148.59,78.74
N$448  (via drill 0.8 pad 1.78)
  other vias: 151.13,78.74
N$449  (via drill 0.8 pad 1.78)
  other vias: 151.13,81.28
N$450  (via drill 0.8 pad 1.78)
  other vias: 148.59,81.28
N$451  (via drill 0.8 pad 1.78)
  other vias: 146.05,81.28
N$452  (via drill 0.8 pad 1.78)
  other vias: 143.51,81.28
N$453  (via drill 0.8 pad 1.78)
  other vias: 140.97,81.28
N$454  (via drill 0.8 pad 1.78)
  other vias: 140.97,83.82
N$455  (via drill 0.8 pad 1.78)
  other vias: 143.51,83.82
N$456  (via drill 0.8 pad 1.78)
  other vias: 146.05,83.82
N$457  (via drill 0.8 pad 1.78)
  other vias: 148.59,83.82
N$458  (via drill 0.8 pad 1.78)
  other vias: 151.13,83.82
N$459  (via drill 0.8 pad 1.78)
  other vias: 151.13,86.36
N$460  (via drill 0.8 pad 1.78)
  other vias: 151.13,88.9
N$461  (via drill 0.8 pad 1.78)
  other vias: 148.59,88.9
N$462  (via drill 0.8 pad 1.78)
  other vias: 148.59,86.36
N$463  (via drill 0.8 pad 1.78)
  other vias: 146.05,86.36
N$464  (via drill 0.8 pad 1.78)
  other vias: 146.05,88.9
N$465  (via drill 0.8 pad 1.78)
  other vias: 143.51,88.9
N$466  (via drill 0.8 pad 1.78)
  other vias: 140.97,88.9
N$467  (via drill 0.8 pad 1.78)
  other vias: 140.97,86.36
N$468  (via drill 0.8 pad 1.78)
  other vias: 143.51,86.36
N$469  (via drill 0.8 pad 1.78)
  other vias: 153.67,88.9
N$470  (via drill 0.8 pad 1.78)
  other vias: 153.67,86.36
N$471  (via drill 0.8 pad 1.78)
  other vias: 153.67,83.82
N$472  (via drill 0.8 pad 1.78)
  other vias: 153.67,81.28
N$473  (via drill 0.8 pad 1.78)
  other vias: 156.21,81.28
N$474  (via drill 0.8 pad 1.78)
  other vias: 156.21,83.82
N$475  (via drill 0.8 pad 1.78)
  other vias: 156.21,86.36
N$476  (via drill 0.8 pad 1.78)
  other vias: 156.21,88.9
N$477  (via drill 0.8 pad 1.78)
  other vias: 118.11,86.36
N$478  (via drill 0.8 pad 1.78)
  other vias: 118.11,88.9
N$479  (via drill 0.8 pad 1.78)
  other vias: 118.11,91.44
N$480  (via drill 0.8 pad 1.78)
  other vias: 120.65,86.36
N$481  (via drill 0.8 pad 1.78)
  other vias: 123.19,86.36
N$482  (via drill 0.8 pad 1.78)
  other vias: 123.19,88.9
N$483  (via drill 0.8 pad 1.78)
  other vias: 120.65,88.9
N$484  (via drill 0.8 pad 1.78)
  other vias: 120.65,91.44
N$485  (via drill 0.8 pad 1.78)
  other vias: 123.19,91.44
N$486  (via drill 0.8 pad 1.78)
  other vias: 115.57,86.36
N$487  (via drill 0.8 pad 1.78)
  other vias: 115.57,88.9
N$488  (via drill 0.8 pad 1.78)
  other vias: 115.57,91.44
N$489  (via drill 0.8 pad 1.78)
  other vias: 113.03,91.44
N$490  (via drill 0.8 pad 1.78)
  other vias: 110.49,91.44
N$491  (via drill 0.8 pad 1.78)
  other vias: 110.49,88.9
N$492  (via drill 0.8 pad 1.78)
  other vias: 113.03,88.9
N$493  (via drill 0.8 pad 1.78)
  other vias: 113.03,86.36
N$494  (via drill 0.8 pad 1.78)
  other vias: 110.49,86.36
N$495  (via drill 0.8 pad 1.78)
  other vias: 107.95,86.36
N$496  (via drill 0.8 pad 1.78)
  other vias: 105.41,86.36
N$497  (via drill 0.8 pad 1.78)
  other vias: 102.87,86.36
N$498  (via drill 0.8 pad 1.78)
  other vias: 100.33,86.36
N$499  (via drill 0.8 pad 1.78)
  other vias: 97.79,86.36
N$500  (via drill 0.8 pad 1.78)
  other vias: 95.25,86.36
N$501  (via drill 0.8 pad 1.78)
  other vias: 107.95,88.9
N$502  (via drill 0.8 pad 1.78)
  other vias: 105.41,88.9
N$503  (via drill 0.8 pad 1.78)
  other vias: 102.87,88.9
N$504  (via drill 0.8 pad 1.78)
  other vias: 100.33,88.9
N$505  (via drill 0.8 pad 1.78)
  other vias: 97.79,88.9
N$506  (via drill 0.8 pad 1.78)
  other vias: 97.79,91.44
N$507  (via drill 0.8 pad 1.78)
  other vias: 100.33,91.44
N$508  (via drill 0.8 pad 1.78)
  other vias: 102.87,91.44
N$509  (via drill 0.8 pad 1.78)
  other vias: 105.41,91.44
N$510  (via drill 0.8 pad 1.78)
  other vias: 107.95,91.44
N$511  (via drill 0.8 pad 1.78)
  other vias: 85.09,93.98
N$512  (via drill 0.8 pad 1.78)
  other vias: 85.09,91.44
N$513  (via drill 0.8 pad 1.78)
  other vias: 85.09,88.9
N$514  (via drill 0.8 pad 1.78)
  other vias: 87.63,88.9
N$515  (via drill 0.8 pad 1.78)
  other vias: 87.63,91.44
N$516  (via drill 0.8 pad 1.78)
  other vias: 87.63,93.98
N$517  (via drill 0.8 pad 1.78)
  other vias: 97.79,93.98
N$518  (via drill 0.8 pad 1.78)
  other vias: 95.25,93.98
N$519  (via drill 0.8 pad 1.78)
  other vias: 92.71,93.98
N$520  (via drill 0.8 pad 1.78)
  other vias: 90.17,93.98
N$521  (via drill 0.8 pad 1.78)
  other vias: 90.17,91.44
N$522  (via drill 0.8 pad 1.78)
  other vias: 92.71,91.44
N$523  (via drill 0.8 pad 1.78)
  other vias: 95.25,91.44
N$524  (via drill 0.8 pad 1.78)
  other vias: 95.25,88.9
N$525  (via drill 0.8 pad 1.78)
  other vias: 92.71,88.9
N$526  (via drill 0.8 pad 1.78)
  other vias: 90.17,88.9
N$527  (via drill 0.8 pad 1.78)
  other vias: 100.33,93.98
N$528  (via drill 0.8 pad 1.78)
  other vias: 151.13,93.98
N$529  (via drill 0.8 pad 1.78)
  other vias: 148.59,93.98
N$530  (via drill 0.8 pad 1.78)
  other vias: 146.05,93.98
N$531  (via drill 0.8 pad 1.78)
  other vias: 143.51,93.98
N$532  (via drill 0.8 pad 1.78)
  other vias: 140.97,93.98
N$533  (via drill 0.8 pad 1.78)
  other vias: 138.43,93.98
N$534  (via drill 0.8 pad 1.78)
  other vias: 135.89,93.98
N$535  (via drill 0.8 pad 1.78)
  other vias: 133.35,93.98
N$536  (via drill 0.8 pad 1.78)
  other vias: 130.81,93.98
N$537  (via drill 0.8 pad 1.78)
  other vias: 128.27,93.98
N$538  (via drill 0.8 pad 1.78)
  other vias: 125.73,93.98
N$539  (via drill 0.8 pad 1.78)
  other vias: 123.19,93.98
N$540  (via drill 0.8 pad 1.78)
  other vias: 120.65,93.98
N$541  (via drill 0.8 pad 1.78)
  other vias: 118.11,93.98
N$542  (via drill 0.8 pad 1.78)
  other vias: 115.57,93.98
N$543  (via drill 0.8 pad 1.78)
  other vias: 113.03,93.98
N$544  (via drill 0.8 pad 1.78)
  other vias: 110.49,93.98
N$545  (via drill 0.8 pad 1.78)
  other vias: 107.95,93.98
N$546  (via drill 0.8 pad 1.78)
  other vias: 105.41,93.98
N$547  (via drill 0.8 pad 1.78)
  other vias: 102.87,93.98
N$548  (via drill 0.8 pad 1.78)
  other vias: 59.69,55.88
N$549  (via drill 0.8 pad 1.78)
  other vias: 57.15,55.88
N$550  (via drill 0.8 pad 1.78)
  other vias: 54.61,55.88
N$551  (via drill 0.8 pad 1.78)
  other vias: 52.07,55.88
N$552  (via drill 0.8 pad 1.78)
  other vias: 49.53,55.88
N$553  (via drill 0.8 pad 1.78)
  other vias: 46.99,55.88
N$554  (via drill 0.8 pad 1.78)
  other vias: 44.45,55.88
N$555  (via drill 0.8 pad 1.78)
  other vias: 41.91,55.88
N$556  (via drill 0.8 pad 1.78)
  other vias: 39.37,55.88
N$557  (via drill 0.8 pad 1.78)
  other vias: 36.83,55.88
N$558  (via drill 0.8 pad 1.78)
  other vias: 34.29,55.88
N$559  (via drill 0.8 pad 1.78)
  other vias: 31.75,55.88
N$560  (via drill 0.8 pad 1.78)
  other vias: 29.21,55.88
N$561  (via drill 0.8 pad 1.78)
  other vias: 26.67,55.88
N$562  (via drill 0.8 pad 1.78)
  other vias: 24.13,55.88
N$563  (via drill 0.8 pad 1.78)
  other vias: 21.59,55.88
N$564  (via drill 0.8 pad 1.78)
  other vias: 19.05,55.88
N$565  (via drill 0.8 pad 1.78)
  other vias: 16.51,55.88
N$566  (via drill 0.8 pad 1.78)
  other vias: 13.97,55.88
N$567  (via drill 0.8 pad 1.78)
  other vias: 11.43,55.88
N$568  (via drill 0.8 pad 1.78)
  other vias: 8.89,55.88
N$569  (via drill 0.8 pad 1.78)
  other vias: 6.35,55.88
N$570  (via drill 0.8 pad 1.78)
  other vias: 3.81,55.88
N$571  (via drill 0.8 pad 1.78)
  other vias: 3.81,58.42
N$572  (via drill 0.8 pad 1.78)
  other vias: 36.83,58.42
N$573  (via drill 0.8 pad 1.78)
  other vias: 36.83,60.96
N$574  (via drill 0.8 pad 1.78)
  other vias: 36.83,63.5
N$575  (via drill 0.8 pad 1.78)
  other vias: 36.83,66.04
N$576  (via drill 0.8 pad 1.78)
  other vias: 36.83,68.58
N$577  (via drill 0.8 pad 1.78)
  other vias: 36.83,71.12
N$578  (via drill 0.8 pad 1.78)
  other vias: 34.29,71.12
N$579  (via drill 0.8 pad 1.78)
  other vias: 34.29,68.58
N$580  (via drill 0.8 pad 1.78)
  other vias: 34.29,66.04
N$581  (via drill 0.8 pad 1.78)
  other vias: 34.29,63.5
N$582  (via drill 0.8 pad 1.78)
  other vias: 34.29,60.96
N$583  (via drill 0.8 pad 1.78)
  other vias: 34.29,58.42
N$584  (via drill 0.8 pad 1.78)
  other vias: 39.37,58.42
N$585  (via drill 0.8 pad 1.78)
  other vias: 39.37,60.96
N$586  (via drill 0.8 pad 1.78)
  other vias: 41.91,58.42
N$587  (via drill 0.8 pad 1.78)
  other vias: 44.45,58.42
N$588  (via drill 0.8 pad 1.78)
  other vias: 46.99,58.42
N$589  (via drill 0.8 pad 1.78)
  other vias: 49.53,58.42
N$590  (via drill 0.8 pad 1.78)
  other vias: 52.07,58.42
N$591  (via drill 0.8 pad 1.78)
  other vias: 54.61,58.42
N$592  (via drill 0.8 pad 1.78)
  other vias: 57.15,58.42
N$593  (via drill 0.8 pad 1.78)
  other vias: 59.69,58.42
N$594  (via drill 0.8 pad 1.78)
  other vias: 62.23,58.42
N$595  (via drill 0.8 pad 1.78)
  other vias: 64.77,58.42
N$596  (via drill 0.8 pad 1.78)
  other vias: 64.77,60.96
N$597  (via drill 0.8 pad 1.78)
  other vias: 62.23,60.96
N$598  (via drill 0.8 pad 1.78)
  other vias: 59.69,60.96
N$599  (via drill 0.8 pad 1.78)
  other vias: 57.15,60.96
N$600  (via drill 0.8 pad 1.78)
  other vias: 54.61,60.96
N$601  (via drill 0.8 pad 1.78)
  other vias: 52.07,60.96
N$602  (via drill 0.8 pad 1.78)
  other vias: 49.53,60.96
N$603  (via drill 0.8 pad 1.78)
  other vias: 46.99,60.96
N$604  (via drill 0.8 pad 1.78)
  other vias: 44.45,60.96
N$605  (via drill 0.8 pad 1.78)
  other vias: 41.91,60.96
N$606  (via drill 0.8 pad 1.78)
  other vias: 64.77,63.5
N$607  (via drill 0.8 pad 1.78)
  other vias: 62.23,63.5
N$608  (via drill 0.8 pad 1.78)
  other vias: 59.69,63.5
N$609  (via drill 0.8 pad 1.78)
  other vias: 57.15,63.5
N$610  (via drill 0.8 pad 1.78)
  other vias: 57.15,71.12
N$611  (via drill 0.8 pad 1.78)
  other vias: 57.15,68.58
N$612  (via drill 0.8 pad 1.78)
  other vias: 57.15,66.04
N$613  (via drill 0.8 pad 1.78)
  other vias: 59.69,66.04
N$614  (via drill 0.8 pad 1.78)
  other vias: 59.69,68.58
N$615  (via drill 0.8 pad 1.78)
  other vias: 59.69,71.12
N$616  (via drill 0.8 pad 1.78)
  other vias: 62.23,71.12
N$617  (via drill 0.8 pad 1.78)
  other vias: 62.23,68.58
N$618  (via drill 0.8 pad 1.78)
  other vias: 62.23,66.04
N$619  (via drill 0.8 pad 1.78)
  other vias: 64.77,66.04
N$620  (via drill 0.8 pad 1.78)
  other vias: 64.77,68.58
N$621  (via drill 0.8 pad 1.78)
  other vias: 64.77,71.12
N$622  (via drill 0.8 pad 1.78)
  other vias: 54.61,71.12
N$623  (via drill 0.8 pad 1.78)
  other vias: 54.61,68.58
N$624  (via drill 0.8 pad 1.78)
  other vias: 54.61,66.04
N$625  (via drill 0.8 pad 1.78)
  other vias: 21.59,68.58
N$626  (via drill 0.8 pad 1.78)
  other vias: 54.61,63.5
N$627  (via drill 0.8 pad 1.78)
  other vias: 52.07,63.5
N$628  (via drill 0.8 pad 1.78)
  other vias: 49.53,63.5
N$629  (via drill 0.8 pad 1.78)
  other vias: 46.99,63.5
N$630  (via drill 0.8 pad 1.78)
  other vias: 44.45,63.5
N$631  (via drill 0.8 pad 1.78)
  other vias: 41.91,63.5
N$632  (via drill 0.8 pad 1.78)
  other vias: 39.37,63.5
N$633  (via drill 0.8 pad 1.78)
  other vias: 39.37,66.04
N$634  (via drill 0.8 pad 1.78)
  other vias: 41.91,66.04
N$635  (via drill 0.8 pad 1.78)
  other vias: 44.45,66.04
N$636  (via drill 0.8 pad 1.78)
  other vias: 46.99,66.04
N$637  (via drill 0.8 pad 1.78)
  other vias: 46.99,68.58
N$638  (via drill 0.8 pad 1.78)
  other vias: 46.99,71.12
N$639  (via drill 0.8 pad 1.78)
  other vias: 44.45,71.12
N$640  (via drill 0.8 pad 1.78)
  other vias: 44.45,68.58
N$641  (via drill 0.8 pad 1.78)
  other vias: 41.91,68.58
N$642  (via drill 0.8 pad 1.78)
  other vias: 39.37,68.58
N$643  (via drill 0.8 pad 1.78)
  other vias: 39.37,71.12
N$644  (via drill 0.8 pad 1.78)
  other vias: 41.91,71.12
N$645  (via drill 0.8 pad 1.78)
  other vias: 49.53,71.12
N$646  (via drill 0.8 pad 1.78)
  other vias: 52.07,71.12
N$647  (via drill 0.8 pad 1.78)
  other vias: 52.07,68.58
N$648  (via drill 0.8 pad 1.78)
  other vias: 52.07,66.04
N$649  (via drill 0.8 pad 1.78)
  other vias: 49.53,66.04
N$650  (via drill 0.8 pad 1.78)
  other vias: 49.53,68.58
N$651  (via drill 0.8 pad 1.78)
  other vias: 24.13,58.42
N$652  (via drill 0.8 pad 1.78)
  other vias: 24.13,60.96
N$653  (via drill 0.8 pad 1.78)
  other vias: 24.13,63.5
N$654  (via drill 0.8 pad 1.78)
  other vias: 24.13,66.04
N$655  (via drill 0.8 pad 1.78)
  other vias: 24.13,68.58
N$656  (via drill 0.8 pad 1.78)
  other vias: 24.13,71.12
N$657  (via drill 0.8 pad 1.78)
  other vias: 26.67,71.12
N$658  (via drill 0.8 pad 1.78)
  other vias: 26.67,68.58
N$659  (via drill 0.8 pad 1.78)
  other vias: 26.67,66.04
N$660  (via drill 0.8 pad 1.78)
  other vias: 26.67,63.5
N$661  (via drill 0.8 pad 1.78)
  other vias: 26.67,60.96
N$662  (via drill 0.8 pad 1.78)
  other vias: 26.67,58.42
N$663  (via drill 0.8 pad 1.78)
  other vias: 29.21,58.42
N$664  (via drill 0.8 pad 1.78)
  other vias: 31.75,58.42
N$665  (via drill 0.8 pad 1.78)
  other vias: 31.75,60.96
N$666  (via drill 0.8 pad 1.78)
  other vias: 29.21,60.96
N$667  (via drill 0.8 pad 1.78)
  other vias: 29.21,63.5
N$668  (via drill 0.8 pad 1.78)
  other vias: 31.75,66.04
N$669  (via drill 0.8 pad 1.78)
  other vias: 31.75,63.5
N$670  (via drill 0.8 pad 1.78)
  other vias: 31.75,68.58
N$671  (via drill 0.8 pad 1.78)
  other vias: 29.21,68.58
N$672  (via drill 0.8 pad 1.78)
  other vias: 29.21,66.04
N$673  (via drill 0.8 pad 1.78)
  other vias: 29.21,71.12
N$674  (via drill 0.8 pad 1.78)
  other vias: 31.75,71.12
N$675  (via drill 0.8 pad 1.78)
  other vias: 59.69,78.74
N$676  (via drill 0.8 pad 1.78)
  other vias: 62.23,78.74
N$677  (via drill 0.8 pad 1.78)
  other vias: 64.77,78.74
N$678  (via drill 0.8 pad 1.78)
  other vias: 24.13,78.74
N$679  (via drill 0.8 pad 1.78)
  other vias: 26.67,78.74
N$680
  Bottom 0.813: 39.37,55.88 39.37,71.12
N$681  (via drill 0.8 pad 1.78)
  other vias: 31.75,78.74
N$682  (via drill 0.8 pad 1.78)
  other vias: 34.29,78.74
N$683  (via drill 0.8 pad 1.78)
  other vias: 36.83,78.74
N$684  (via drill 0.8 pad 1.78)
  other vias: 39.37,78.74
N$685  (via drill 0.8 pad 1.78)
  other vias: 41.91,78.74
N$686  (via drill 0.8 pad 1.78)
  other vias: 44.45,78.74
N$687  (via drill 0.8 pad 1.78)
  other vias: 57.15,78.74
N$688  (via drill 0.8 pad 1.78)
  other vias: 54.61,78.74
N$689  (via drill 0.8 pad 1.78)
  other vias: 52.07,78.74
N$690  (via drill 0.8 pad 1.78)
  other vias: 49.53,78.74
N$691  (via drill 0.8 pad 1.78)
  other vias: 46.99,78.74
N$692  (via drill 0.8 pad 1.78)
  other vias: 46.99,81.28
N$693  (via drill 0.8 pad 1.78)
  other vias: 44.45,81.28
N$694  (via drill 0.8 pad 1.78)
  other vias: 41.91,81.28
N$695  (via drill 0.8 pad 1.78)
  other vias: 39.37,81.28
N$696  (via drill 0.8 pad 1.78)
  other vias: 36.83,81.28
N$697  (via drill 0.8 pad 1.78)
  other vias: 34.29,81.28
N$698  (via drill 0.8 pad 1.78)
  other vias: 31.75,81.28
N$699  (via drill 0.8 pad 1.78)
  other vias: 29.21,81.28
N$700  (via drill 0.8 pad 1.78)
  other vias: 26.67,81.28
N$701  (via drill 0.8 pad 1.78)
